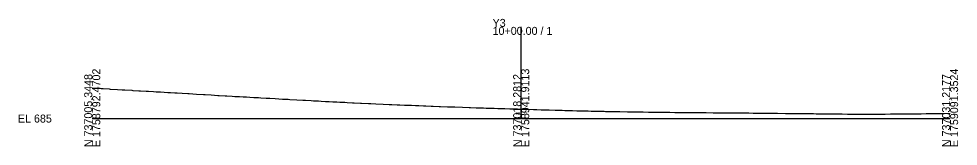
# Model space of a CAD drawing. Extents: x -26 to 1760432, y -10 to 737112.
# Drawn here: x -25.7 to 302.8, y -9.7 to 35 of the extents above; entities that cross this region are included whole.
import ezdxf

# ---------------------------------------------------------------- set-up
doc = ezdxf.new("R2010")
doc.units = 0
for name, color, linetype in [('Default', 7, 'Continuous'), ('Exist Cross Section Cell', 7, 'Continuous'), ('Exist XS Center Line Elevation Label', 7, 'Continuous'), ('Exist XS Ground Line', 7, 'Continuous')]:
    doc.layers.add(name, color=color, linetype=linetype)

msp = doc.modelspace()

# ---------------------------------------------------------------- linework, layer by layer
at = {"layer": 'Exist Cross Section Cell'}
for p, q in [((150, 0), (150, 32.11)), ((0, 0), (150, 0)), ((150, 0), (300, 0))]:
    msp.add_line(p, q, dxfattribs=at)
at = {"layer": 'Exist XS Ground Line'}
msp.add_lwpolyline([(0, 10.7), (0.41, 10.68), (1.28, 10.63), (3.16, 10.53), (3.79, 10.49), (5.91, 10.36), (6.3, 10.34), (8.81, 10.19), (10.5, 10.1), (11.4, 10.05), (13.83, 9.89), (14.15, 9.88), (16.34, 9.74), (16.89, 9.71), (18.85, 9.6), (19.64, 9.55), (21.36, 9.45), (22.39, 9.4), (23.87, 9.31), (25.14, 9.23), (26.38, 9.16), (27.42, 9.1), (28.89, 9.02), (29.73, 8.97), (31.4, 8.88), (33.38, 8.76), (33.91, 8.73), (36.42, 8.58), (38.92, 8.45), (39.48, 8.41), (41.62, 8.28), (43.94, 8.13), (44.37, 8.1), (46.45, 7.99), (47.11, 7.96), (48.96, 7.84), (49.86, 7.78), (51.47, 7.7), (52.83, 7.62), (53.98, 7.56), (55.14, 7.5), (56.49, 7.42), (58.1, 7.32), (59, 7.27), (60.85, 7.17), (61.51, 7.13), (62.06, 7.1), (64.02, 6.98), (66.53, 6.84), (68.47, 6.74), (69.09, 6.71), (71.55, 6.57), (73.61, 6.45), (74.06, 6.43), (74.58, 6.4), (76.57, 6.3), (77.33, 6.25), (79.07, 6.16), (80.08, 6.11), (81.58, 6.03), (82.83, 5.97), (84.09, 5.91), (85.57, 5.84), (86.6, 5.78), (88.32, 5.7), (89.11, 5.65), (91.07, 5.56), (91.62, 5.53), (93.81, 5.43), (94.13, 5.41), (96.64, 5.3), (97.46, 5.25), (99.22, 5.15), (101.78, 5.04), (103.85, 4.96), (104.17, 4.95), (104.8, 4.92), (106.68, 4.84), (107.55, 4.81), (109.19, 4.74), (110.3, 4.69), (111.7, 4.64), (113.05, 4.58), (114.21, 4.53), (115.79, 4.47), (116.71, 4.44), (118.54, 4.38), (119.22, 4.35), (121.29, 4.27), (121.73, 4.26), (124.24, 4.16), (126.45, 4.09), (126.78, 4.08), (129.53, 3.97), (131.77, 3.88), (132.28, 3.87), (134.28, 3.8), (135.02, 3.77), (136.79, 3.72), (137.77, 3.68), (139.3, 3.64), (140.52, 3.6), (141.81, 3.55), (143.26, 3.51), (144.32, 3.48), (146.01, 3.42), (146.83, 3.4), (148.76, 3.35), (149.34, 3.33), (150, 3.31), (151.51, 3.25), (151.85, 3.24), (154.35, 3.16), (155.44, 3.13), (157, 3.09), (159.37, 3.03), (159.75, 3.02), (161.88, 2.95), (162.49, 2.93), (164.39, 2.9), (165.24, 2.88), (166.9, 2.83), (167.99, 2.79), (169.41, 2.75), (170.74, 2.73), (171.92, 2.71), (173.48, 2.67), (174.43, 2.64), (176.23, 2.6), (176.94, 2.58), (178.98, 2.54), (179.45, 2.53), (181.96, 2.48), (184.47, 2.43), (187.22, 2.39), (189.49, 2.36), (189.97, 2.35), (192, 2.32), (192.71, 2.31), (194.5, 2.28), (195.46, 2.27), (197.01, 2.24), (198.21, 2.23), (199.52, 2.23), (200.95, 2.22), (202.03, 2.2), (203.7, 2.18), (204.54, 2.17), (206.45, 2.15), (207.05, 2.15), (209.2, 2.13), (209.56, 2.12), (212.07, 2.1), (213.41, 2.08), (214.69, 2.07), (217.09, 2.06), (217.44, 2.06), (219.6, 2.03), (220.18, 2.03), (222.11, 2.03), (222.93, 2.02), (224.62, 2), (225.68, 2), (227.13, 1.99), (228.43, 1.97), (229.64, 1.95), (231.17, 1.94), (232.14, 1.93), (233.92, 1.92), (234.65, 1.92), (236.67, 1.88), (237.16, 1.88), (239.67, 1.86), (242.4, 1.83), (244.91, 1.81), (247.2, 1.8), (247.66, 1.8), (249.71, 1.78), (250.4, 1.77), (252.22, 1.74), (253.15, 1.71), (254.73, 1.7), (255.9, 1.69), (257.24, 1.68), (258.64, 1.67), (259.75, 1.65), (261.39, 1.62), (262.26, 1.61), (264.14, 1.59), (264.77, 1.58), (266.89, 1.55), (267.28, 1.55), (269.78, 1.52), (271.39, 1.51), (272.38, 1.5), (274.8, 1.51), (275.13, 1.52), (277.31, 1.57), (279.15, 1.6), (279.82, 1.62), (280.62, 1.63), (282.33, 1.65), (283.37, 1.65), (284.84, 1.64), (286.12, 1.66), (287.35, 1.68), (288.86, 1.69), (289.86, 1.7), (291.61, 1.73), (292.37, 1.74), (294.36, 1.78), (294.88, 1.79), (297.39, 1.82), (300, 1.88)], dxfattribs=at)

# ---------------------------------------------------------------- texts
at = {"layer": 'Default'}
msp.add_text('-', height=0.0001, dxfattribs=at).set_placement((0, 0))
at = {"layer": 'Exist Cross Section Cell'}
for s, p in [('Y3', (140, 32.11)), ('10+00.00 / 1', (140, 29.31)), ('EL 685', (-26, -1.4))]:
    msp.add_text(s, height=2.8, dxfattribs=at).set_placement(p)
for s, p in [('E 1758792.4702', (2.8, -10)), ('E 1758941.9113', (152.8, -10)), ('E 1759091.3524', (302.8, -10)), ('N 737005.3448', (0, -10)), ('N 737018.2812', (150, -10)), ('N 737031.2177', (300, -10))]:
    msp.add_text(s, height=2.8, rotation=90, dxfattribs=at).set_placement(p)
at = {"layer": 'Exist XS Center Line Elevation Label'}
msp.add_text('688.31', height=1, dxfattribs=at).set_placement((148.04, 1.31))

doc.saveas('drawing.dxf')
